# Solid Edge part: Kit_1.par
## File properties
Sűrűség: 0,000 kg/m^3
Pontosság: 0,990
Author: ahadarics
Last saved by: ahadarics
Revision: 76
Username: ahadarics
Dokumentum tartalom típus: 0
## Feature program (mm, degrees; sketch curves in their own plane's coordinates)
base feature "unnamed BaseFeature 1"
thread "unnamed Thread 1"
chamfer "unnamed Chamfer 1"
sketch for "Furat_1" plane through (0, -48.5, 12) normal (0, 0, 1) x-axis (0, 1, 0)
  hole centre (-0.25, 0) bore radius 4.283
hole "Furat_1" nominal diameter 9.728 finite  ThreadDepth = 7.5 mm
chamfer "Letörés_2" setback 0.7
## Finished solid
Body 1: solid body, 49 faces, 54 edges, 8 vertices.
  Faces by surface: plane 15, cylinder 14, cone 13, torus 7
  Edges by curve: circle 46, intersection 4, line 4
Bounding box of the edges (mm; curved faces can reach further): 27.000 x 37.500 x 25.500, from (-13.5, -76.25, -13.5) to (13.5, -38.75, 12).
Cylindrical faces by radius (mm): R4.15 x1, R4.25 x1, R4.28 x1, R4.283 x1, R4.55 x1, R6 x1, R6.05 x1, R7.05 x1, R7.1 x1, R9.85 x1, R11 x2, R11.1 x1, R13.5 x1
Conical faces (half-angle, radius in mm at the cone's reference point): 0.1788 deg R5.7706 x1, 15 deg R7.05 x1, 19.7315 deg R4.0176 x1, 20.542 deg R4.55 x1, 21.5244 deg R5.2703 x1, 24.3997 deg R4.55 x1, 45 deg R4.983 x1, 45 deg R6.15 x1, 45 deg R6.2 x1, 45 deg R11 x1, 59 deg R2.1415 x2, 60 deg R10.425 x1
Toroidal faces (ring radius, tube radius in mm): R4.2 r0.2 x1, R4.3 r0.3 x1, R5.6424 r0.4 x1, R5.85 r0.2 x1, R6.85 r0.2 x1, R6.9 r0.2 x2
Planar faces by outward normal: +y 5, +z 2, -y 8
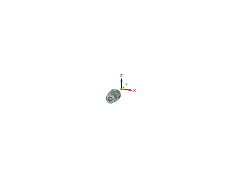
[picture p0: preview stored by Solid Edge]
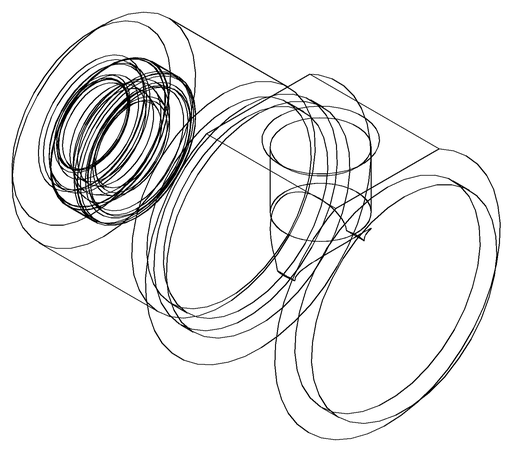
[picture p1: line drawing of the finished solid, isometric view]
